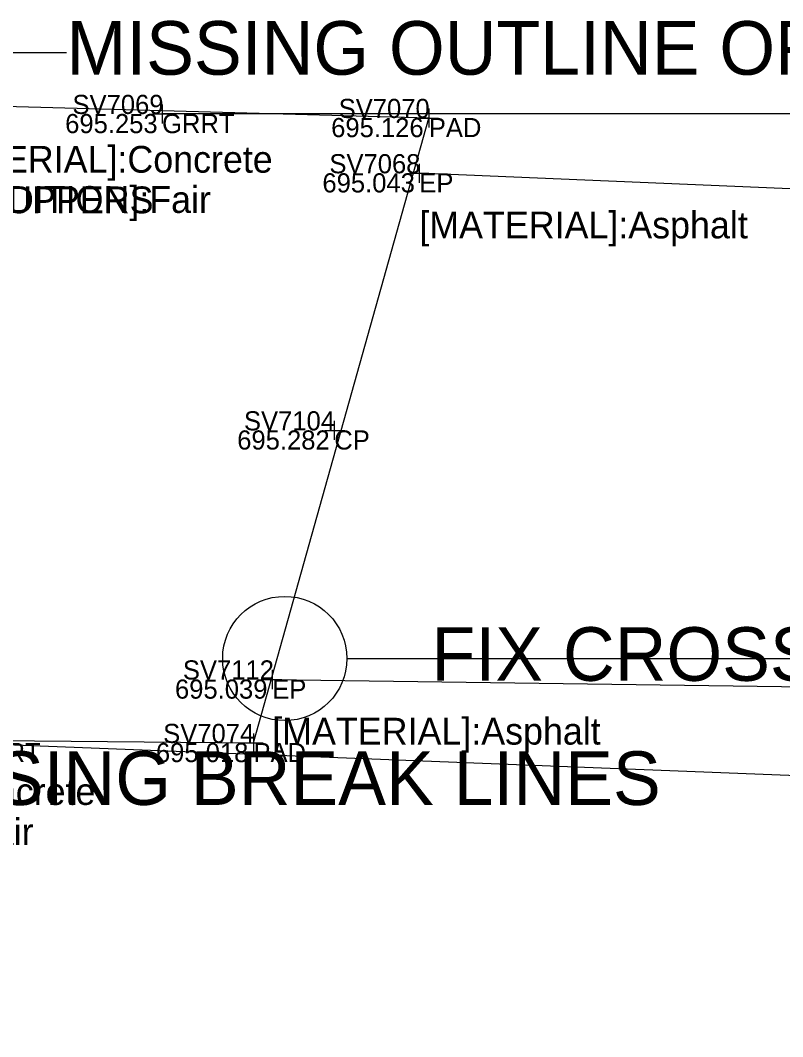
# Model space of a CAD drawing. Extents: x 1660019 to 1662995, y 619975 to 620342.
# Drawn here: x 1661530.4 to 1661570.3, y 620196.4 to 620249.5 of the extents above; entities that cross this region are included whole.
import ezdxf

# ---------------------------------------------------------------- set-up
doc = ezdxf.new("R2010")
doc.units = 0
for name, color, linetype in [('BR_X_Rail_Object', 7, 'Continuous'), ('PV_X_EOP', 7, 'Continuous'), ('RD_P_GR_Lt', 7, 'Continuous'), ('RD_X_Concrete_Pad', 7, 'Continuous'), ('RD_X_GR_Bar', 7, 'Continuous'), ('RD_X_GR_Rt', 7, 'Continuous'), ('RD_X_Wall', 7, 'Continuous'), ('SC_Scratch6', 7, 'Continuous'), ('SV_X_Text', 7, 'Continuous')]:
    doc.layers.add(name, color=color, linetype=linetype)

msp = doc.modelspace()

# ---------------------------------------------------------------- linework, layer by layer
at = {"layer": 'PV_X_EOP'}
for points in [[(1662111.666, 620229.323), (1662054.932, 620230.37), (1661998.416, 620231.316), (1661945.734, 620232.161), (1661885.467, 620233.497), (1661831.108, 620234.651), (1661773.238, 620235.895), (1661719.204, 620236.817), (1661662.345, 620238.107), (1661602.461, 620239.354), (1661551.289, 620241.52)], [(1661543.603, 620215.075), (1661595.452, 620214.355), (1661653.935, 620213.409), (1661707.721, 620212.244), (1661760.969, 620211.015), (1661840.686, 620209.322), (1661897.276, 620208.314), (1661955.799, 620207.498), (1662009.836, 620206.218), (1662063.331, 620205.168), (1662115.706, 620204.212)]]:
    msp.add_lwpolyline(points, dxfattribs=at)
at = {"layer": 'RD_P_GR_Lt'}
for p, q in [((1661537.844, 620245.118), (1661537.844, 620244.118)), ((1661551.786, 620244.908), (1661551.786, 620243.908)), ((1661537.344, 620244.618), (1661538.344, 620244.618)), ((1661537.844, 620244.618), (1661537.844, 620244.618)), ((1661551.286, 620244.408), (1661552.286, 620244.408)), ((1661551.786, 620244.408), (1661551.786, 620244.408)), ((1661551.289, 620242.02), (1661551.289, 620241.02)), ((1661550.789, 620241.52), (1661551.789, 620241.52)), ((1661551.289, 620241.52), (1661551.289, 620241.52)), ((1661546.845, 620228.588), (1661546.845, 620227.588)), ((1661546.345, 620228.088), (1661547.345, 620228.088)), ((1661546.845, 620228.088), (1661546.845, 620228.088)), ((1661543.603, 620215.575), (1661543.603, 620214.575)), ((1661543.103, 620215.075), (1661544.103, 620215.075)), ((1661543.603, 620215.075), (1661543.603, 620215.075)), ((1661542.622, 620212.259), (1661542.622, 620211.259)), ((1661542.122, 620211.759), (1661543.122, 620211.759)), ((1661542.622, 620211.759), (1661542.622, 620211.759))]:
    msp.add_line(p, q, dxfattribs=at)
at = {"layer": 'RD_X_Concrete_Pad'}
msp.add_lwpolyline([(1661551.786, 620244.408), (1661525.769, 620245.111), (1661515.918, 620212.007), (1661542.622, 620211.759)], close=True, dxfattribs=at)
at = {"layer": 'RD_X_GR_Rt'}
for points in [[(1662112.146, 620237.065), (1662055.657, 620238.252), (1661999.678, 620239.27), (1661943.73, 620240.204), (1661887.333, 620241.474), (1661831.01, 620242.219), (1661774.889, 620243.801), (1661718.605, 620244.369), (1661662.444, 620245.383), (1661601.891, 620244.641), (1661537.844, 620244.618)], [(1661527.713, 620211.763), (1661596.627, 620209.068), (1661652.773, 620205.714), (1661709.087, 620204.454), (1661758.9, 620203.473), (1661840.536, 620201.815), (1661896.268, 620200.971), (1661955.332, 620199.483), (1662008.565, 620198.59), (1662063.032, 620197.376), (1662114.916, 620196.417)]]:
    msp.add_lwpolyline(points, dxfattribs=at)
at = {"layer": 'SC_Scratch6'}
for p, q in [((1661528.424, 620247.836), (1661532.853, 620247.836)), ((1661547.502, 620216.173), (1661588.462, 620216.173))]:
    msp.add_line(p, q, dxfattribs=at)
msp.add_circle((1661544.257, 620216.173), 3.245, dxfattribs=at)

# ---------------------------------------------------------------- texts
at = {"layer": 'BR_X_Rail_Object'}
for s, p in [('GRRT', (1661537.844, 620243.618)), ('PAD', (1661551.786, 620243.408)), ('EP', (1661551.289, 620240.52)), ('CP', (1661546.845, 620227.088)), ('EP', (1661543.603, 620214.075)), ('GRRT', (1661527.713, 620210.763)), ('PAD', (1661542.622, 620210.759))]:
    msp.add_text(s, height=1, dxfattribs=at).set_placement(p)
at = {"layer": 'RD_X_GR_Bar'}
for s, p in [('695.253', (1661532.78, 620243.618)), ('695.126', (1661546.682, 620243.408)), ('695.043', (1661546.225, 620240.52)), ('695.282', (1661541.772, 620227.088)), ('695.039', (1661538.519, 620214.075)), ('695.018', (1661537.522, 620210.759))]:
    msp.add_text(s, height=1, dxfattribs=at).set_placement(p)
at = {"layer": 'RD_X_Wall'}
for s, p in [('SV7069', (1661533.162, 620244.618)), ('SV7070', (1661547.074, 620244.408)), ('SV7068', (1661546.59, 620241.52)), ('SV7104', (1661542.125, 620228.088)), ('SV7112', (1661538.931, 620215.075)), ('SV7074', (1661537.902, 620211.759))]:
    msp.add_text(s, height=1, dxfattribs=at).set_placement(p)
at = {"layer": 'SC_Scratch6'}
for s, p in [('MISSING OUTLINE OF ABUTMENT', (1661532.853, 620246.669)), ('FIX CROSSING LINES', (1661551.931, 620215.007)), ('MISSING BREAK LINES', (1661522.501, 620208.522))]:
    msp.add_text(s, height=2.79999, dxfattribs=at).set_placement(p)
at = {"layer": 'SV_X_Text'}
for s, p in [('[MATERIAL]:Concrete', (1661525.109, 620241.55)), ('[NOTE]:SCUPPERS', (1661520.336, 620239.43)), ('[CONDITION]:Fair', (1661525.109, 620239.45)), ('[MATERIAL]:Asphalt', (1661551.289, 620238.12)), ('[MATERIAL]:Asphalt', (1661543.603, 620211.675)), ('[MATERIAL]:Concrete', (1661515.842, 620208.522)), ('[CONDITION]:Fair', (1661515.842, 620206.422))]:
    msp.add_text(s, height=1.4, dxfattribs=at).set_placement(p)

doc.saveas('drawing.dxf')
